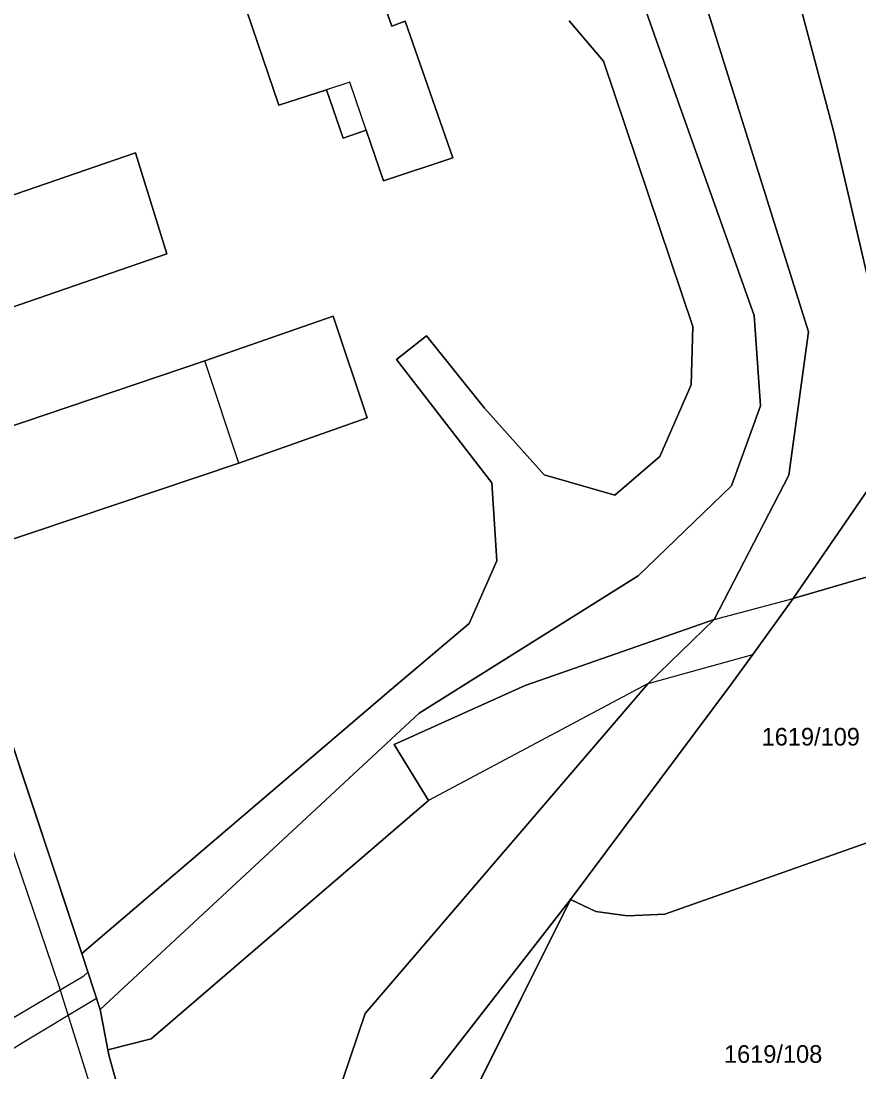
# Model space of a CAD drawing. Extents: x -263943 to -261149, y -1236934 to -1230686.
# Drawn here: x -262385.9 to -262290.8, y -1236543.6 to -1236424.4 of the extents above; entities that cross this region are included whole.
import ezdxf

# ---------------------------------------------------------------- set-up
doc = ezdxf.new("R2010")
doc.units = 0
for name, color, linetype in [('body_kn', 7, 'Continuous'), ('kladpar_druhypozemkov', 7, 'Continuous'), ('kladpar_hranice', 7, 'Continuous'), ('kladpar_parcelnecisla', 7, 'Continuous'), ('kladpar_plochy', 7, 'Continuous'), ('tarchy_linie', 7, 'Continuous'), ('zappar_hrandruhpozemk', 7, 'Continuous')]:
    doc.layers.add(name, color=color, linetype=linetype)

msp = doc.modelspace()

# ---------------------------------------------------------------- linework, layer by layer
at = {"layer": 'body_kn'}
for p, q in [((-262342.31, -1236424.45), (-262342.31, -1236424.45)), ((-262343.83, -1236425.04), (-262343.83, -1236425.04)), ((-262313.77, -1236426.7), (-262313.77, -1236426.7)), ((-262319.79, -1236428.98), (-262319.79, -1236428.98)), ((-262348.58, -1236431.39), (-262348.58, -1236431.39)), ((-262351.25, -1236432.26), (-262351.25, -1236432.26)), ((-262356.63, -1236434), (-262356.63, -1236434)), ((-262349.35, -1236437.74), (-262349.35, -1236437.74)), ((-262346.74, -1236436.82), (-262346.74, -1236436.82)), ((-262346.74, -1236436.82), (-262346.74, -1236436.82)), ((-262293.72, -1236436.91), (-262293.72, -1236436.91)), ((-262372.89, -1236439.39), (-262372.89, -1236439.39)), ((-262336.91, -1236439.97), (-262336.91, -1236439.97)), ((-262344.78, -1236442.58), (-262344.78, -1236442.58)), ((-262369.35, -1236450.84), (-262369.35, -1236450.84)), ((-262350.48, -1236457.91), (-262350.48, -1236457.91)), ((-262302.72, -1236457.83), (-262302.72, -1236457.83)), ((-262309.67, -1236459.09), (-262309.67, -1236459.09)), ((-262339.9, -1236460.13), (-262339.9, -1236460.13)), ((-262296.54, -1236459.7), (-262296.54, -1236459.7)), ((-262365.05, -1236462.97), (-262365.05, -1236462.97)), ((-262343.29, -1236462.84), (-262343.29, -1236462.84)), ((-262309.84, -1236465.7), (-262309.84, -1236465.7)), ((-262333.3, -1236468.37), (-262333.3, -1236468.37)), ((-262301.97, -1236468.08), (-262301.97, -1236468.08)), ((-262346.6, -1236469.44), (-262346.6, -1236469.44)), ((-262361.17, -1236474.59), (-262361.17, -1236474.59)), ((-262361.17, -1236474.59), (-262361.17, -1236474.59)), ((-262313.41, -1236473.83), (-262313.41, -1236473.83)), ((-262326.54, -1236475.92), (-262326.54, -1236475.92)), ((-262332.47, -1236476.84), (-262332.47, -1236476.84)), ((-262298.76, -1236475.97), (-262298.76, -1236475.97)), ((-262318.5, -1236478.22), (-262318.5, -1236478.22)), ((-262305.29, -1236477.15), (-262305.29, -1236477.15)), ((-262305.29, -1236477.15), (-262305.29, -1236477.15)), ((-262331.89, -1236485.66), (-262331.89, -1236485.66)), ((-262315.88, -1236487.38), (-262315.88, -1236487.38)), ((-262298.27, -1236489.96), (-262298.27, -1236489.96)), ((-262307.25, -1236492.31), (-262307.25, -1236492.31)), ((-262307.25, -1236492.31), (-262307.25, -1236492.31)), ((-262335.03, -1236492.77), (-262335.03, -1236492.77)), ((-262302.86, -1236496.31), (-262302.86, -1236496.31)), ((-262314.74, -1236499.57), (-262314.74, -1236499.57)), ((-262314.74, -1236499.57), (-262314.74, -1236499.57)), ((-262343.86, -1236500.22), (-262343.86, -1236500.22)), ((-262328.69, -1236499.82), (-262328.69, -1236499.82)), ((-262305.4, -1236499.78), (-262305.4, -1236499.78)), ((-262340.73, -1236502.94), (-262340.73, -1236502.94)), ((-262343.54, -1236506.5), (-262343.54, -1236506.5)), ((-262339.65, -1236512.86), (-262339.65, -1236512.86)), ((-262323.54, -1236524.07), (-262323.54, -1236524.07)), ((-262323.54, -1236524.07), (-262323.54, -1236524.07)), ((-262320.66, -1236525.46), (-262320.66, -1236525.46)), ((-262317.09, -1236525.94), (-262317.09, -1236525.94)), ((-262312.85, -1236525.76), (-262312.85, -1236525.76)), ((-262379.01, -1236530.21), (-262379.01, -1236530.21)), ((-262378.76, -1236532.73), (-262378.76, -1236532.73)), ((-262378.31, -1236532.32), (-262378.31, -1236532.32)), ((-262381.6, -1236533.82), (-262381.6, -1236533.82)), ((-262377.33, -1236535.3), (-262377.33, -1236535.3)), ((-262376.9, -1236536.58), (-262376.9, -1236536.58)), ((-262346.84, -1236537.03), (-262346.84, -1236537.03)), ((-262371.14, -1236539.89), (-262371.14, -1236539.89)), ((-262385.76, -1236540.39), (-262385.76, -1236540.39)), ((-262376.03, -1236541.14), (-262376.03, -1236541.14)), ((-262375.9, -1236541.84), (-262375.9, -1236541.84))]:
    msp.add_line(p, q, dxfattribs=at)
at = {"layer": 'kladpar_druhypozemkov'}
for p, q in [((-262295.95, -1236504.22), (-262295.95, -1236504.22)), ((-262300.4, -1236540.15), (-262300.4, -1236540.15))]:
    msp.add_line(p, q, dxfattribs=at)
at = {"layer": 'kladpar_hranice'}
for points in [[(-262233.64, -1236470.84), (-262247.57, -1236438.1), (-262274.68, -1236447.2), (-262286.75, -1236486.59), (-262298.27, -1236489.96), (-262287.67, -1236474.47), (-262288.41, -1236459.63), (-262293.72, -1236436.91), (-262301.97, -1236405.71), (-262319.44, -1236361.69), (-262320.37, -1236359.23), (-262327.61, -1236343.85), (-262325.86, -1236343.2), (-262275.87, -1236325.74), (-262263.3, -1236360.18), (-262252.93, -1236389.61), (-262245.33, -1236410.55)], [(-262307.25, -1236492.31), (-262328.69, -1236499.82), (-262343.54, -1236506.5), (-262339.65, -1236512.86), (-262371.14, -1236539.89), (-262376.03, -1236541.14), (-262376.9, -1236536.58), (-262340.73, -1236502.94), (-262315.88, -1236487.38), (-262305.29, -1236477.15), (-262301.97, -1236468.08), (-262302.72, -1236457.83), (-262313.77, -1236426.7), (-262337.06, -1236360.64), (-262337.81, -1236356.14), (-262336.45, -1236350.21), (-262335.43, -1236346.74), (-262333.92, -1236346.18), (-262328.34, -1236362.01), (-262327.53, -1236364.43), (-262311.13, -1236413.15), (-262296.54, -1236459.7), (-262298.76, -1236475.97), (-262307.25, -1236492.31)], [(-262337.06, -1236360.64), (-262313.77, -1236426.7), (-262302.72, -1236457.83), (-262301.97, -1236468.08), (-262305.29, -1236477.15)], [(-262301.97, -1236405.71), (-262293.72, -1236436.91), (-262288.41, -1236459.63), (-262287.67, -1236474.47)], [(-262324.57, -1236675.43), (-262331.26, -1236656.18), (-262355.27, -1236588.58), (-262357.1, -1236567.29), (-262346.84, -1236537.03), (-262314.74, -1236499.57), (-262307.25, -1236492.31), (-262298.76, -1236475.97), (-262296.54, -1236459.7), (-262311.13, -1236413.15)], [(-262347.59, -1236414.25), (-262343.83, -1236425.04), (-262342.31, -1236424.45), (-262336.91, -1236439.97), (-262344.78, -1236442.58), (-262346.74, -1236436.82), (-262349.35, -1236437.74), (-262351.25, -1236432.26), (-262356.63, -1236434), (-262363.29, -1236414.41)], [(-262363.29, -1236414.41), (-262356.63, -1236434), (-262351.25, -1236432.26), (-262349.35, -1236437.74), (-262346.74, -1236436.82), (-262344.78, -1236442.58)], [(-262344.78, -1236442.58), (-262336.91, -1236439.97), (-262342.31, -1236424.45), (-262343.83, -1236425.04), (-262347.59, -1236414.25)], [(-262323.68, -1236424.4), (-262319.79, -1236428.98), (-262309.67, -1236459.09), (-262309.84, -1236465.7), (-262313.41, -1236473.83), (-262318.5, -1236478.22), (-262326.54, -1236475.92), (-262333.3, -1236468.37), (-262339.9, -1236460.13), (-262343.29, -1236462.84), (-262332.47, -1236476.84), (-262331.89, -1236485.66), (-262335.03, -1236492.77), (-262343.86, -1236500.22), (-262379.01, -1236530.21), (-262393.87, -1236485.55), (-262361.17, -1236474.59), (-262346.6, -1236469.44), (-262350.48, -1236457.91), (-262365.05, -1236462.97), (-262388.18, -1236470.81)], [(-262305.29, -1236477.15), (-262315.88, -1236487.38), (-262340.73, -1236502.94), (-262376.9, -1236536.58), (-262379.01, -1236530.21), (-262343.86, -1236500.22), (-262335.03, -1236492.77), (-262331.89, -1236485.66), (-262332.47, -1236476.84), (-262343.29, -1236462.84), (-262339.9, -1236460.13), (-262333.3, -1236468.37), (-262326.54, -1236475.92), (-262318.5, -1236478.22), (-262313.41, -1236473.83), (-262309.84, -1236465.7), (-262309.67, -1236459.09), (-262319.79, -1236428.98), (-262323.68, -1236424.4)], [(-262388.18, -1236470.81), (-262365.05, -1236462.97), (-262350.48, -1236457.91), (-262346.6, -1236469.44), (-262361.17, -1236474.59), (-262393.87, -1236485.55), (-262405.76, -1236450.69), (-262372.89, -1236439.39), (-262369.35, -1236450.84), (-262392.39, -1236458.77), (-262388.18, -1236470.81)], [(-262392.39, -1236458.77), (-262369.35, -1236450.84), (-262372.89, -1236439.39), (-262405.76, -1236450.69)], [(-262287.67, -1236474.47), (-262298.27, -1236489.96), (-262302.86, -1236496.31), (-262305.4, -1236499.78), (-262323.54, -1236524.07), (-262339.55, -1236544.66), (-262347.77, -1236574.85), (-262344.15, -1236593.68), (-262333.33, -1236623.45), (-262323.02, -1236651.61), (-262316.25, -1236671.62)], [(-262323.54, -1236524.07), (-262305.4, -1236499.78), (-262302.86, -1236496.31), (-262298.27, -1236489.96), (-262286.75, -1236486.59), (-262282.48, -1236485.32), (-262280.83, -1236489.84), (-262282.26, -1236491.74), (-262284.77, -1236496.51), (-262285.58, -1236501.19), (-262282.2, -1236514.93), (-262312.85, -1236525.76), (-262317.09, -1236525.94), (-262320.66, -1236525.46), (-262323.54, -1236524.07)], [(-262393.87, -1236485.55), (-262379.01, -1236530.21), (-262376.9, -1236536.58), (-262376.03, -1236541.14), (-262375.9, -1236541.84), (-262370, -1236563.13), (-262361.9, -1236591.03), (-262349.05, -1236629.97), (-262323.5, -1236701.72)], [(-262307.25, -1236492.31), (-262314.74, -1236499.57), (-262346.84, -1236537.03), (-262357.1, -1236567.29), (-262355.27, -1236588.58), (-262331.26, -1236656.18), (-262324.57, -1236675.43), (-262320.6, -1236688.24), (-262310.95, -1236717.07), (-262308.08, -1236725.11), (-262314.12, -1236728.13), (-262323.5, -1236701.72), (-262349.05, -1236629.97), (-262361.9, -1236591.03), (-262370, -1236563.13), (-262375.9, -1236541.84), (-262376.03, -1236541.14), (-262371.14, -1236539.89), (-262339.65, -1236512.86), (-262343.54, -1236506.5), (-262328.69, -1236499.82), (-262307.25, -1236492.31)], [(-262341.38, -1236564.93), (-262334.72, -1236546.45), (-262323.54, -1236524.07), (-262320.66, -1236525.46), (-262317.09, -1236525.94), (-262312.85, -1236525.76), (-262282.2, -1236514.93), (-262269.92, -1236550.04), (-262342.39, -1236575.65)], [(-262300.07, -1236700.2), (-262296.76, -1236709.02), (-262297.28, -1236712.24), (-262301.05, -1236713.72), (-262306.09, -1236700.2), (-262316.25, -1236671.62), (-262323.02, -1236651.61), (-262333.33, -1236623.45), (-262344.15, -1236593.68), (-262347.77, -1236574.85), (-262339.55, -1236544.66), (-262323.54, -1236524.07), (-262334.72, -1236546.45), (-262341.38, -1236564.93), (-262342.42, -1236575.19), (-262342.39, -1236575.65), (-262341.1, -1236593.68), (-262332.22, -1236618.36), (-262329, -1236621.16), (-262327.12, -1236626.3), (-262322.86, -1236637.95), (-262318.43, -1236650.08), (-262311.15, -1236670.01), (-262300.07, -1236700.2)]]:
    msp.add_lwpolyline(points, dxfattribs=at)
at = {"layer": 'kladpar_plochy'}
for p, q in [((-262363.29, -1236414.41), (-262356.63, -1236434)), ((-262343.83, -1236425.04), (-262347.59, -1236414.25)), ((-262342.31, -1236424.45), (-262343.83, -1236425.04)), ((-262336.91, -1236439.97), (-262342.31, -1236424.45)), ((-262323.68, -1236424.4), (-262319.79, -1236428.98)), ((-262319.79, -1236428.98), (-262309.67, -1236459.09)), ((-262356.63, -1236434), (-262351.25, -1236432.26)), ((-262351.25, -1236432.26), (-262349.35, -1236437.74)), ((-262349.35, -1236437.74), (-262346.74, -1236436.82)), ((-262346.74, -1236436.82), (-262344.78, -1236442.58)), ((-262372.89, -1236439.39), (-262405.76, -1236450.69)), ((-262369.35, -1236450.84), (-262372.89, -1236439.39)), ((-262344.78, -1236442.58), (-262336.91, -1236439.97)), ((-262392.39, -1236458.77), (-262369.35, -1236450.84)), ((-262350.48, -1236457.91), (-262365.05, -1236462.97)), ((-262346.6, -1236469.44), (-262350.48, -1236457.91)), ((-262309.67, -1236459.09), (-262309.84, -1236465.7)), ((-262339.9, -1236460.13), (-262343.29, -1236462.84)), ((-262333.3, -1236468.37), (-262339.9, -1236460.13)), ((-262365.05, -1236462.97), (-262388.18, -1236470.81)), ((-262343.29, -1236462.84), (-262332.47, -1236476.84)), ((-262309.84, -1236465.7), (-262313.41, -1236473.83)), ((-262326.54, -1236475.92), (-262333.3, -1236468.37)), ((-262361.17, -1236474.59), (-262346.6, -1236469.44)), ((-262393.87, -1236485.55), (-262361.17, -1236474.59)), ((-262313.41, -1236473.83), (-262318.5, -1236478.22)), ((-262318.5, -1236478.22), (-262326.54, -1236475.92)), ((-262332.47, -1236476.84), (-262331.89, -1236485.66)), ((-262379.01, -1236530.21), (-262393.87, -1236485.55)), ((-262393.87, -1236485.55), (-262379.01, -1236530.21)), ((-262331.89, -1236485.66), (-262335.03, -1236492.77)), ((-262335.03, -1236492.77), (-262343.86, -1236500.22)), ((-262343.86, -1236500.22), (-262379.01, -1236530.21)), ((-262312.85, -1236525.76), (-262282.2, -1236514.93)), ((-262334.72, -1236546.45), (-262323.54, -1236524.07)), ((-262323.54, -1236524.07), (-262320.66, -1236525.46)), ((-262320.66, -1236525.46), (-262317.09, -1236525.94)), ((-262317.09, -1236525.94), (-262312.85, -1236525.76)), ((-262379.01, -1236530.21), (-262376.9, -1236536.58)), ((-262376.9, -1236536.58), (-262376.03, -1236541.14)), ((-262376.03, -1236541.14), (-262375.9, -1236541.84)), ((-262375.9, -1236541.84), (-262370, -1236563.13))]:
    msp.add_line(p, q, dxfattribs=at)
for points in [[(-262245.33, -1236410.55), (-262241.77, -1236409.2), (-262231.18, -1236405.32), (-262228.39, -1236403.38), (-262224.93, -1236398.48), (-262213.69, -1236431.21), (-262203.65, -1236460.13), (-262211.11, -1236462.49), (-262233.64, -1236470.84), (-262247.57, -1236438.1), (-262274.68, -1236447.2), (-262286.75, -1236486.59), (-262298.27, -1236489.96), (-262287.67, -1236474.47), (-262288.41, -1236459.63), (-262293.72, -1236436.91), (-262301.97, -1236405.71), (-262319.44, -1236361.69), (-262320.37, -1236359.23), (-262327.61, -1236343.85), (-262325.86, -1236343.2), (-262275.87, -1236325.74), (-262263.3, -1236360.18), (-262252.93, -1236389.61)], [(-262307.25, -1236492.31), (-262328.69, -1236499.82), (-262343.54, -1236506.5), (-262339.65, -1236512.86), (-262371.14, -1236539.89), (-262376.03, -1236541.14), (-262376.9, -1236536.58), (-262340.73, -1236502.94), (-262315.88, -1236487.38), (-262305.29, -1236477.15), (-262301.97, -1236468.08), (-262302.72, -1236457.83), (-262313.77, -1236426.7), (-262337.06, -1236360.64), (-262337.81, -1236356.14), (-262336.45, -1236350.21), (-262335.43, -1236346.74), (-262333.92, -1236346.18), (-262328.34, -1236362.01), (-262327.53, -1236364.43), (-262311.13, -1236413.15), (-262296.54, -1236459.7), (-262298.76, -1236475.97)], [(-262388.18, -1236470.81), (-262365.05, -1236462.97), (-262350.48, -1236457.91), (-262346.6, -1236469.44), (-262361.17, -1236474.59), (-262393.87, -1236485.55), (-262405.76, -1236450.69), (-262372.89, -1236439.39), (-262369.35, -1236450.84), (-262392.39, -1236458.77)], [(-262323.54, -1236524.07), (-262305.4, -1236499.78), (-262302.86, -1236496.31), (-262298.27, -1236489.96), (-262286.75, -1236486.59), (-262282.48, -1236485.32), (-262280.83, -1236489.84), (-262282.26, -1236491.74), (-262284.77, -1236496.51), (-262285.58, -1236501.19), (-262282.2, -1236514.93), (-262312.85, -1236525.76), (-262317.09, -1236525.94), (-262320.66, -1236525.46)], [(-262307.25, -1236492.31), (-262314.74, -1236499.57), (-262346.84, -1236537.03), (-262357.1, -1236567.29), (-262355.27, -1236588.58), (-262331.26, -1236656.18), (-262324.57, -1236675.43), (-262320.6, -1236688.24), (-262310.95, -1236717.07), (-262308.08, -1236725.11), (-262314.12, -1236728.13), (-262323.5, -1236701.72), (-262349.05, -1236629.97), (-262361.9, -1236591.03), (-262370, -1236563.13), (-262375.9, -1236541.84), (-262376.03, -1236541.14), (-262371.14, -1236539.89), (-262339.65, -1236512.86), (-262343.54, -1236506.5), (-262328.69, -1236499.82)], [(-262300.07, -1236700.2), (-262296.76, -1236709.02), (-262297.28, -1236712.24), (-262301.05, -1236713.72), (-262306.09, -1236700.2), (-262316.25, -1236671.62), (-262323.02, -1236651.61), (-262333.33, -1236623.45), (-262344.15, -1236593.68), (-262347.77, -1236574.85), (-262339.55, -1236544.66), (-262323.54, -1236524.07), (-262334.72, -1236546.45), (-262341.38, -1236564.93), (-262342.42, -1236575.19), (-262342.39, -1236575.65), (-262341.1, -1236593.68), (-262332.22, -1236618.36), (-262329, -1236621.16), (-262327.12, -1236626.3), (-262322.86, -1236637.95), (-262318.43, -1236650.08), (-262311.15, -1236670.01)]]:
    msp.add_lwpolyline(points, close=True, dxfattribs=at)
for points in [[(-262337.06, -1236360.64), (-262313.77, -1236426.7), (-262302.72, -1236457.83), (-262301.97, -1236468.08), (-262305.29, -1236477.15), (-262315.88, -1236487.38), (-262340.73, -1236502.94), (-262376.9, -1236536.58), (-262379.01, -1236530.21), (-262343.86, -1236500.22), (-262335.03, -1236492.77), (-262331.89, -1236485.66), (-262332.47, -1236476.84), (-262343.29, -1236462.84), (-262339.9, -1236460.13), (-262333.3, -1236468.37), (-262326.54, -1236475.92), (-262318.5, -1236478.22), (-262313.41, -1236473.83), (-262309.84, -1236465.7), (-262309.67, -1236459.09), (-262319.79, -1236428.98), (-262323.68, -1236424.4)], [(-262301.97, -1236405.71), (-262293.72, -1236436.91), (-262288.41, -1236459.63), (-262287.67, -1236474.47), (-262298.27, -1236489.96), (-262302.86, -1236496.31), (-262305.4, -1236499.78), (-262323.54, -1236524.07), (-262339.55, -1236544.66), (-262347.77, -1236574.85), (-262344.15, -1236593.68), (-262333.33, -1236623.45), (-262323.02, -1236651.61), (-262316.25, -1236671.62)], [(-262324.57, -1236675.43), (-262331.26, -1236656.18), (-262355.27, -1236588.58), (-262357.1, -1236567.29), (-262346.84, -1236537.03), (-262314.74, -1236499.57), (-262307.25, -1236492.31), (-262298.76, -1236475.97), (-262296.54, -1236459.7), (-262311.13, -1236413.15)], [(-262347.59, -1236414.25), (-262343.83, -1236425.04), (-262342.31, -1236424.45), (-262336.91, -1236439.97), (-262344.78, -1236442.58), (-262346.74, -1236436.82), (-262349.35, -1236437.74), (-262351.25, -1236432.26), (-262356.63, -1236434), (-262363.29, -1236414.41)]]:
    msp.add_lwpolyline(points, dxfattribs=at)
at = {"layer": 'tarchy_linie'}
msp.add_lwpolyline([(-262389.61, -1236539.22), (-262387.3, -1236537.81), (-262378.76, -1236532.73), (-262378.31, -1236532.32), (-262377.33, -1236535.3), (-262385.76, -1236540.39), (-262388.63, -1236542.14), (-262389.61, -1236539.22)], dxfattribs=at)
at = {"layer": 'zappar_hrandruhpozemk'}
for p, q in [((-262348.58, -1236431.39), (-262351.25, -1236432.26)), ((-262346.74, -1236436.82), (-262348.58, -1236431.39)), ((-262361.17, -1236474.59), (-262365.05, -1236462.97)), ((-262307.25, -1236492.31), (-262298.27, -1236489.96)), ((-262314.74, -1236499.57), (-262302.86, -1236496.31)), ((-262314.74, -1236499.57), (-262339.65, -1236512.86))]:
    msp.add_line(p, q, dxfattribs=at)
msp.add_lwpolyline([(-262373.77, -1236558.79), (-262381.6, -1236533.82), (-262392.84, -1236500.85)], dxfattribs=at)

# ---------------------------------------------------------------- texts
at = {"layer": 'kladpar_parcelnecisla'}
for s, p in [('1619/109', (-262301.86, -1236506.62)), ('1619/108', (-262306.13, -1236542.61))]:
    msp.add_text(s, height=2, dxfattribs=at).set_placement(p)

doc.saveas('drawing.dxf')
